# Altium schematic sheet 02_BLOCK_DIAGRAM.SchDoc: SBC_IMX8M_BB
size A2; CompanyName: Google LLC; Engineer: Bangfei/Michael/Leo; Organization: Google LLC; Address1: 1600 Amphitheatre Parkway; Address2: Mountain View, CA 94043; DocumentNumber: 2; Revision: PVT; SheetNumber: 2; SheetTotal: 11
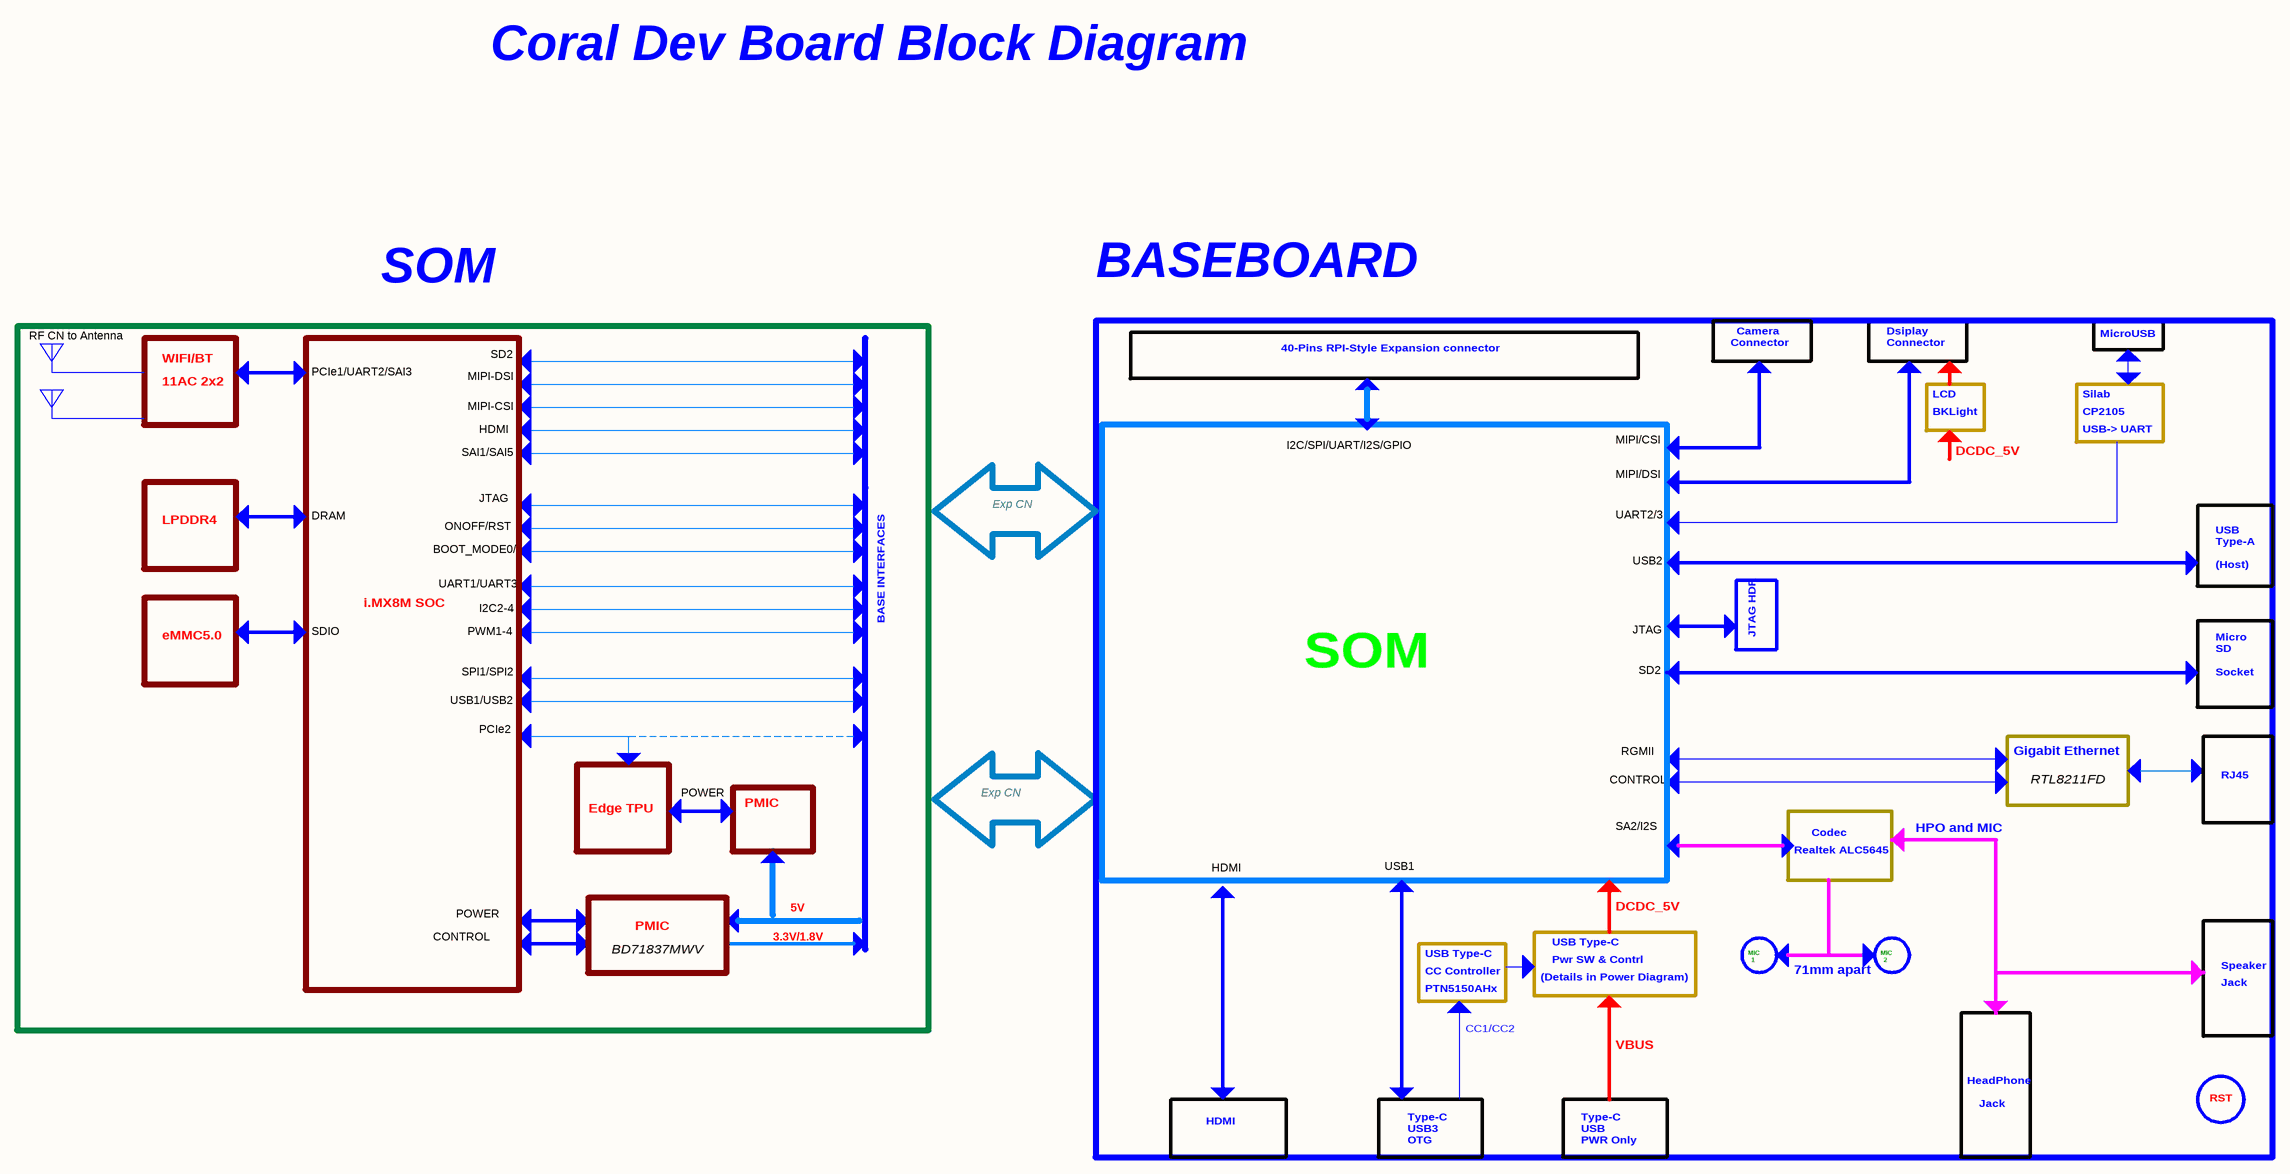
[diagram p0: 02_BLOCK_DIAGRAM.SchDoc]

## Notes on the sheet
- Coral Dev Board Block Diagram
- SOM
- BASEBOARD
- Camera
- Dsiplay
- RF CN to Antenna
- WIFI/BT
- 11AC 2x2
- PCIe1/UART2/SAI3
- MIPI-DSI
- SD2
- 40-Pins RPI-Style Expansion connector
- Connector
- MicroUSB
- MIPI-CSI
- HDMI
- I2C/SPI/UART/I2S/GPIO
- MIPI/CSI
- LCD
- BKLight
- Silab
- CP2105
- USB-> UART
- SAI1/SAI5
- JTAG
- MIPI/DSI
- DCDC_5V
- LPDDR4
- DRAM
- BOOT_MODE0/1
- ONOFF/RST
- Exp CN
- UART2/3
- USB2
- i.MX8M SOC
- UART1/UART3
- I2C2-4
- BASE INTERFACES
- USB
  Type-A
  (Host)
- eMMC5.0
- SDIO
- SPI1/SPI2
- PWM1-4
- JTAG HDR
- Micro SD
  Socket
- USB1/USB2
- PCIe2
- CONTROL
- RGMII
- Gigabit Ethernet
- RTL8211FD
- RJ45
- Edge TPU
- POWER
- PMIC
- SA2/I2S
- Codec
- HPO and MIC
- USB1
- Realtek ALC5645
- BD71837MWV
- 3.3V/1.8V
- 5V
- USB Type-C
- Pwr SW &
- Contrl
- MIC
  1
- MIC
  2
- CC Controller
- PTN5150AHx
- (Details in Power Diagram)
- 71mm apart
- Speaker
- Jack
- CC1/CC2
- VBUS
- HeadPhone
- RST
- Type-C
  USB3
  OTG
- Type-C
  USB
  PWR Only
